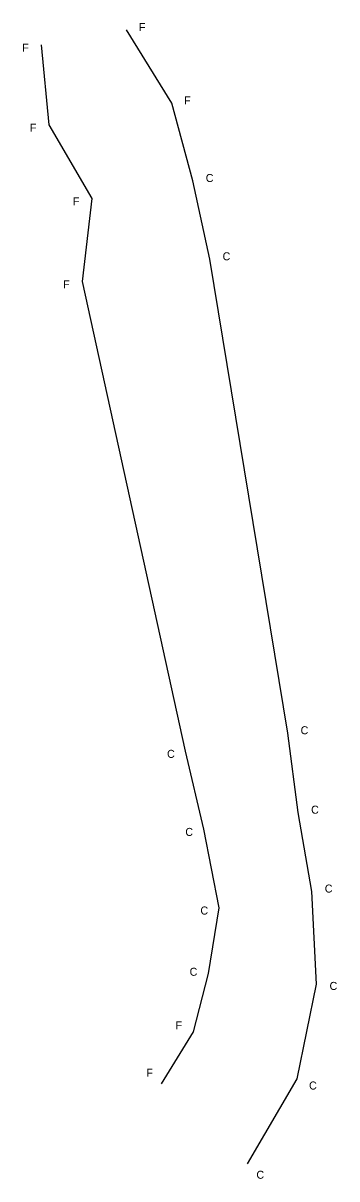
# Model space of a CAD drawing. Extents: x -26 to 1764011, y -10 to 712381.
# Drawn here: x 1763815 to 1764011, y 711659 to 712381 of the extents above; entities that cross this region are included whole.
import ezdxf

# ---------------------------------------------------------------- set-up
doc = ezdxf.new("R2010")
doc.units = 0
for name, color, linetype in [('Prop SS Cut Line', 7, 'Continuous'), ('Prop SS Fill Line', 7, 'Continuous'), ('Prop SS Misc', 7, 'Continuous'), ('Prop SS Transition Line', 7, 'Continuous')]:
    doc.layers.add(name, color=color, linetype=linetype)

msp = doc.modelspace()

# ---------------------------------------------------------------- linework, layer by layer
at = {"layer": 'Prop SS Cut Line'}
for p, q in [((1763931.85, 712233.24), (1763921.33, 712282.15)), ((1763980.55, 711937.2), (1763931.85, 712233.24)), ((1763987.11, 711887.58), (1763980.55, 711937.2)), ((1763928.26, 711877.18), (1763916.84, 711925.94)), ((1763995.66, 711838.32), (1763987.11, 711887.58)), ((1763937.69, 711828.08), (1763928.26, 711877.18)), ((1763998.52, 711780.25), (1763995.66, 711838.32)), ((1763931.05, 711787.08), (1763937.69, 711828.08)), ((1763986.55, 711721.16), (1763998.52, 711780.25)), ((1763955.49, 711668.11), (1763986.55, 711721.16))]:
    msp.add_line(p, q, dxfattribs=at)
at = {"layer": 'Prop SS Fill Line'}
for p, q in [((1763908.23, 712330.61), (1763879.95, 712376.39)), ((1763831.59, 712317.07), (1763826.82, 712367.01)), ((1763858.45, 712271.05), (1763831.59, 712317.07)), ((1763852.33, 712219.19), (1763858.45, 712271.05)), ((1763901.77, 711718.17), (1763921.81, 711750.51))]:
    msp.add_line(p, q, dxfattribs=at)
at = {"layer": 'Prop SS Transition Line'}
for p, q in [((1763921.33, 712282.15), (1763908.23, 712330.61)), ((1763916.84, 711925.94), (1763852.33, 712219.19)), ((1763921.81, 711750.51), (1763931.05, 711787.08))]:
    msp.add_line(p, q, dxfattribs=at)

# ---------------------------------------------------------------- texts
at = {"layer": 'Prop SS Misc'}
for s, p in [('F', (1763887.63, 712375.63)), ('F', (1763814.81, 712362.77)), ('F', (1763915.91, 712329.85)), ('F', (1763819.58, 712312.83)), ('C', (1763929.4, 712281.39)), ('F', (1763846.44, 712266.81)), ('C', (1763939.92, 712232.48)), ('F', (1763840.31, 712214.95)), ('C', (1763988.62, 711936.44)), ('C', (1763905.22, 711921.7)), ('C', (1763995.19, 711886.82)), ('C', (1763916.64, 711872.94)), ('C', (1764003.73, 711837.56)), ('C', (1763926.07, 711823.84)), ('C', (1763919.33, 711785.59)), ('C', (1764006.7, 711776.74)), ('F', (1763910.54, 711752.14)), ('F', (1763892.29, 711722.49)), ('C', (1763993.89, 711714.53)), ('C', (1763961.03, 711658.79))]:
    msp.add_text(s, height=5, dxfattribs=at).set_placement(p)

doc.saveas('drawing.dxf')
